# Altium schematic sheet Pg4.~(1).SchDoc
size 431 x 279 mm; Date: Not shown in title block; ApprovedBy: Not shown in title block; CheckedBy: Not shown in title block; Author: Not shown in title block; CompanyName: Not shown in title block; Engineer: Not shown in title block; Organization: Not shown in title block; Address1: Not shown in title block; Address2: Not shown in title block; Address3: Not shown in title block; Address4: Not shown in title block; DocumentNumber: 4; Revision: Use project parameter SCH_Rev; SheetNumber: 4; SheetTotal: 7; PageSetup: Record=PageOptions|CenterHorizontal=True|CenterVertical=True|PrintScale=0.59|XCorrection=1.00|YCorrection=1.00|PrintKind=0|BorderSize=5000000|LeftOffset=0|BottomOffset=0|Orientation=2|PaperLength=1000|PaperWidth=1000|Scale=100|PaperSource=15|PrintQuality=600|MediaType=1|DitherType=10|PaperKind=Letter|PrintScaleMode=1
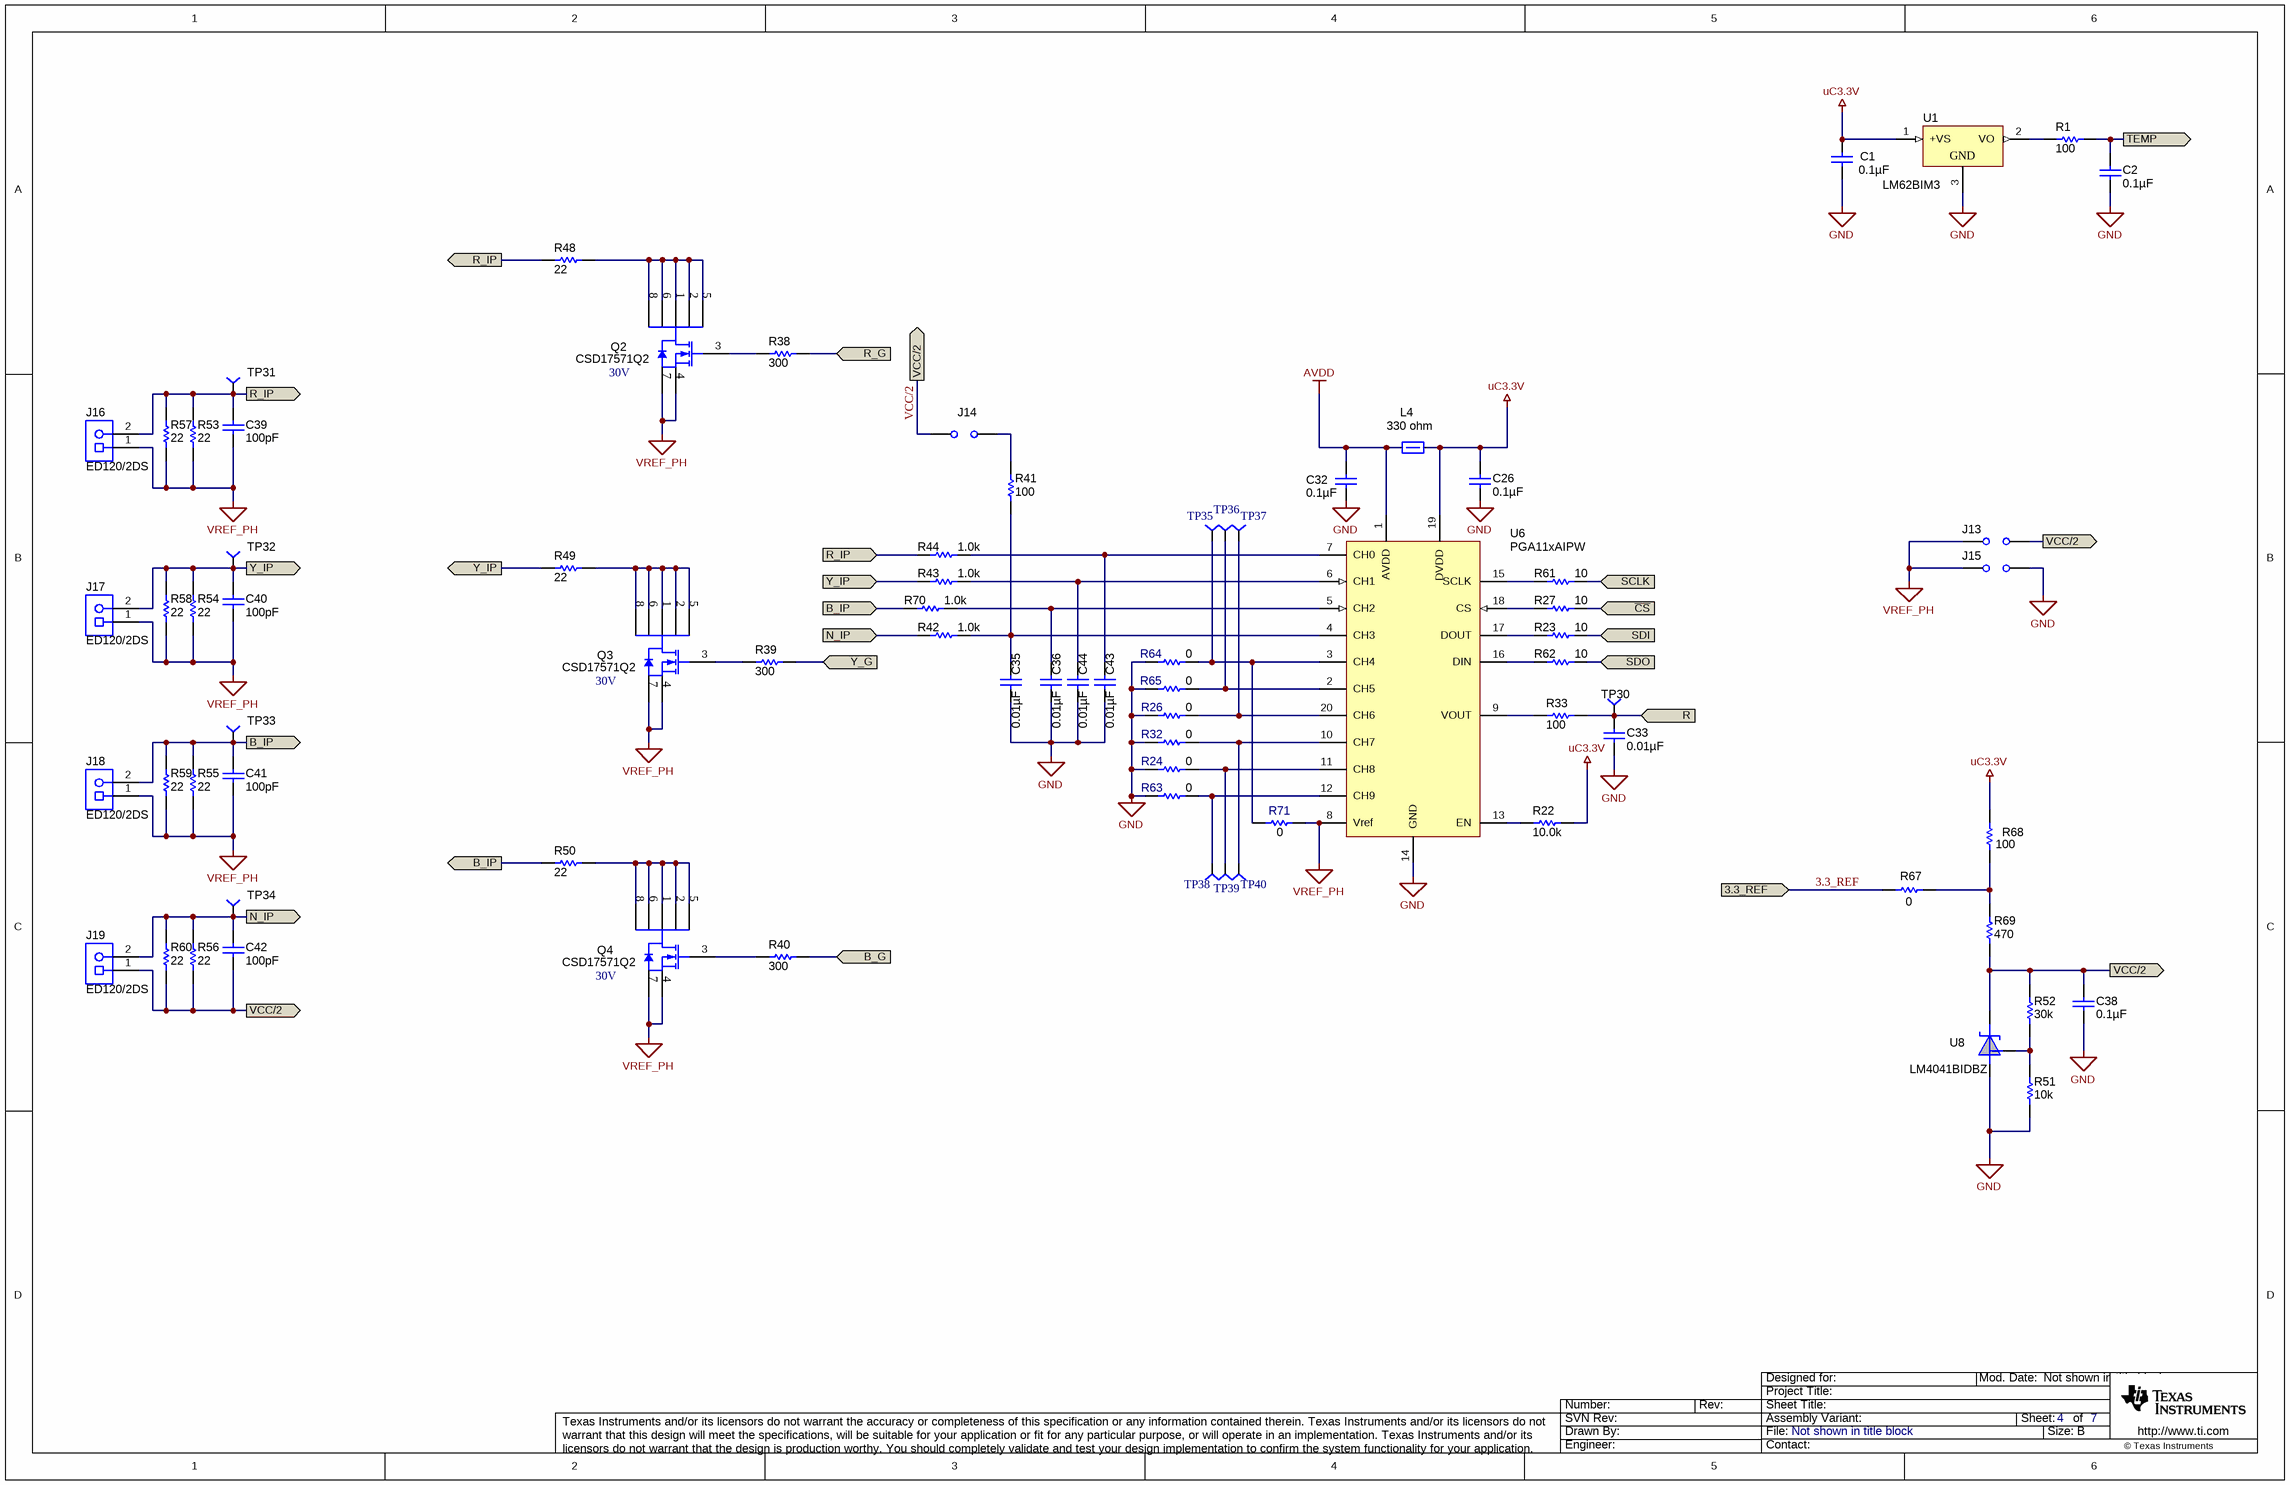
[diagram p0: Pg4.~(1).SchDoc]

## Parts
C1  ValueDisplayed: 0.1µF  [0603]  (hidden comment: 06033C104JAT2A)
C2  ValueDisplayed: 0.1µF  [0603]  (hidden comment: 06033C104JAT2A)
C26  ValueDisplayed: 0.1µF  [0603]  (hidden comment: 06033C104JAT2A)
C32  ValueDisplayed: 0.1µF  [0603]  (hidden comment: 06033C104JAT2A)
C33  ValueDisplayed: 0.01µF  [0603]  (hidden comment: C1608C0G1E103J)
C35  ValueDisplayed: 0.01µF  [0603]  (hidden comment: C1608C0G1E103J)
C36  ValueDisplayed: 0.01µF  [0603]  (hidden comment: C1608C0G1E103J)
C38  ValueDisplayed: 0.1µF  [0603]  (hidden comment: 06033C104JAT2A)
C39  ValueDisplayed: 100pF  [0603]  (hidden comment: 06033C101KAT2A)
C40  ValueDisplayed: 100pF  [0603]  (hidden comment: 06033C101KAT2A)
C41  ValueDisplayed: 100pF  [0603]  (hidden comment: 06033C101KAT2A)
C42  ValueDisplayed: 100pF  [0603]  (hidden comment: 06033C101KAT2A)
C43  ValueDisplayed: 0.01µF  [0603]  (hidden comment: C1608C0G1E103J)
C44  ValueDisplayed: 0.01µF  [0603]  (hidden comment: C1608C0G1E103J)
J13  JUMPER_2X100MIL  [HDR100_1X2]  (value not drawn)
J14  JUMPER_2X100MIL  [HDR100_1X2]  (value not drawn)
J15  JUMPER_2X100MIL  [HDR100_1X2]  (value not drawn)
J16  ED120/2DS  [CONN_ED120-2DS]
J17  ED120/2DS  [CONN_ED120-2DS]
J18  ED120/2DS  [CONN_ED120-2DS]
J19  ED120/2DS  [CONN_ED120-2DS]
L4  value 330 ohm  [0603]  (hidden comment: BLM18SG331TN1D)
Q2  CSD17571Q2  value 30V  [SON_CSD17571Q2]
Q3  CSD17571Q2  value 30V  [SON_CSD17571Q2]
Q4  CSD17571Q2  value 30V  [SON_CSD17571Q2]
R1  value 100  [0603]  (hidden comment: CRCW0603100RFKEA)
R22  value 10.0k  [0603]  (hidden comment: CRCW060310K0FKEA)
R23  value 10  [0603]  (hidden comment: CRCW060310R0JNEA)
R24  value 0  [0603]  (hidden comment: CRCW06030000Z0EA)
R26  value 0  [0603]  (hidden comment: CRCW06030000Z0EA)
R27  value 10  [0603]  (hidden comment: CRCW060310R0JNEA)
R32  value 0  [0603]  (hidden comment: CRCW06030000Z0EA)
R33  value 100  [0603]  (hidden comment: CRCW0603100RFKEA)
R38  value 300  [0603]  (hidden comment: CRCW0603300RJNEA)
R39  value 300  [0603]  (hidden comment: CRCW0603300RJNEA)
R40  value 300  [0603]  (hidden comment: CRCW0603300RJNEA)
R41  value 100  [0603]  (hidden comment: CRCW0603100RFKEA)
R42  value 1.0k  [0603]  (hidden comment: CRCW06031K00JNEA)
R43  value 1.0k  [0603]  (hidden comment: CRCW06031K00JNEA)
R44  value 1.0k  [0603]  (hidden comment: CRCW06031K00JNEA)
R48  value 22  [1206]  (hidden comment: CRCW120622R0JNEA)
R49  value 22  [1206]  (hidden comment: CRCW120622R0JNEA)
R50  value 22  [1206]  (hidden comment: CRCW120622R0JNEA)
R51  value 10k  [0603]  (hidden comment: RNCF0603TKY10K0)
R52  value 30k  [0603]  (hidden comment: CRCW060330K0JNEA)
R53  value 22  [1206]  (hidden comment: CRCW120622R0JNEA)
R54  value 22  [1206]  (hidden comment: CRCW120622R0JNEA)
R55  value 22  [1206]  (hidden comment: CRCW120622R0JNEA)
R56  value 22  [1206]  (hidden comment: CRCW120622R0JNEA)
R57  value 22  [1206]  (hidden comment: CRCW120622R0JNEA)
R58  value 22  [1206]  (hidden comment: CRCW120622R0JNEA)
R59  value 22  [1206]  (hidden comment: CRCW120622R0JNEA)
R60  value 22  [1206]  (hidden comment: CRCW120622R0JNEA)
R61  value 10  [0603]  (hidden comment: CRCW060310R0JNEA)
R62  value 10  [0603]  (hidden comment: CRCW060310R0JNEA)
R63  value 0  [0603]  (hidden comment: CRCW06030000Z0EA)
R64  value 0  [0603]  (hidden comment: CRCW06030000Z0EA)
R65  value 0  [0603]  (hidden comment: CRCW06030000Z0EA)
R67  value 0  [0603]  (hidden comment: CRCW06030000Z0EA)
R68  value 100  [0603]  (hidden comment: CRCW0603100RFKEA)
R69  value 470  [0603]  (hidden comment: CRCW0603470RJNEA)
R70  value 1.0k  [0603]  (hidden comment: CRCW06031K00JNEA)
R71  value 0  [0603]  (hidden comment: CRCW06030000Z0EA)
TP30  TP-040_RND  [TP-040_RND]  (value not drawn)
TP31  TP-040_RND  [TP-040_RND]  (value not drawn)
TP32  TP-040_RND  [TP-040_RND]  (value not drawn)
TP33  TP-040_RND  [TP-040_RND]  (value not drawn)
TP34  TP-040_RND  [TP-040_RND]  (value not drawn)
TP35  TP-040_RND  [TP-040_RND]  (value not drawn)
TP36  TP-040_RND  [TP-040_RND]  (value not drawn)
TP37  TP-040_RND  [TP-040_RND]  (value not drawn)
TP38  TP-040_RND  [TP-040_RND]  (value not drawn)
TP39  TP-040_RND  [TP-040_RND]  (value not drawn)
TP40  TP-040_RND  [TP-040_RND]  (value not drawn)
U1  LM62BIM3  [MF03A_N]
U6  PGA11xAIPW  [PW0020A_L]
U8  LM4041BIDBZ  [SOT-23]

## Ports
3.3_REF (in), B_G (in), B_IP (in), B_IP (out), N_IP (in), N_IP (out), R (in), R_G (in), R_IP (in), R_IP (out), SCLK (in), SDI (in), SDO (in), TEMP (out), VCC/2 (out), Y_G (in), Y_IP (in), Y_IP (out), ~{CS} (in)

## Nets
AVDD: C32.2 L4.1 U6.1(AVDD)
GND: C1.2 C2.1 C26.1 C32.1 C33.2 C35.2 C36.2 C38.1 C43.2 C44.2 J15.2 R24.1 R26.1 R32.1 R51.1 R63.1 R64.1 R65.1 U1.3(GND) U6.14(GND) U8.3(A)
uC3.3V: C1.1 C26.2 L4.2 R22.1 R68.1 U1.1(+VS) U6.19(DVDD)
VREF_PH: C39.2 C40.2 C41.2 J13.1 J15.1 J16.1 J17.1 J18.1 Q2.4(S) Q2.7(S) Q3.4(S) Q3.7(S) Q4.4(S) Q4.7(S) R53.1 R54.1 R55.1 R57.1 R58.1 R59.1 R71.2 U6.8(Vref)
3.3_REF: R67.1 ; port 3.3_REF
~{CS}: R27.2 ; port ~{CS}
B_G: R40.1 ; port B_G
B_IP: C41.1 J18.2 R50.1 R55.2 R59.2 R70.1 TP33.1 ; port B_IP
N_IP: C42.1 J19.2 R42.1 R56.2 R60.2 TP34.1 ; port N_IP
R: C33.1 R33.2 TP30.1 ; port R
R_G: R38.1 ; port R_G
R_IP: C39.1 J16.2 R44.1 R48.1 R53.2 R57.2 TP31.1 ; port R_IP
SCLK: R61.2 ; port SCLK
SDI: R23.2 ; port SDI
SDO: R62.2 ; port SDO
TEMP: C2.2 R1.2 ; port TEMP
VCC/2: C38.2 C42.2 J13.2 J14.2 J19.1 R52.2 R56.1 R60.1 R69.1 U8.2(C) ; port VCC/2
Y_G: R39.1 ; port Y_G
Y_IP: C40.1 J17.2 R43.1 R49.1 R54.2 R58.2 TP32.1 ; port Y_IP
NetC35_1: C35.1 R41.1 R42.2 U6.4(CH3)
NetC36_1: C36.1 R70.2 U6.5(CH2)
NetC43_1: C43.1 R44.2 U6.7(CH0)
NetC44_1: C44.1 R43.2 U6.6(CH1)
NetJ14_1: J14.1 R41.2
NetQ2_1: Q2.1(D) Q2.2(D) Q2.5(D) Q2.6(D) Q2.8(D) R48.2
NetQ2_3: Q2.3(G) R38.2
NetQ3_1: Q3.1(D) Q3.2(D) Q3.5(D) Q3.6(D) Q3.8(D) R49.2
NetQ3_3: Q3.3(G) R39.2
NetQ4_1: Q4.1(D) Q4.2(D) Q4.5(D) Q4.6(D) Q4.8(D) R50.2
NetQ4_3: Q4.3(G) R40.2
NetR1_1: R1.1 U1.2(VO)
NetR22_2: R22.2 U6.13(EN)
NetR23_1: R23.1 U6.17(DOUT)
NetR24_2: R24.2 TP39.1 U6.11(CH8)
NetR26_2: R26.2 TP37.1 U6.20(CH6)
NetR27_1: R27.1 U6.18(CS)
NetR32_2: R32.2 TP40.1 U6.10(CH7)
NetR33_1: R33.1 U6.9(VOUT)
NetR51_2: R51.2 R52.1 U8.1(FB)
NetR61_1: R61.1 U6.15(SCLK)
NetR62_1: R62.1 U6.16(DIN)
NetR63_2: R63.2 TP38.1 U6.12(CH9)
NetR64_2: R64.2 R71.1 TP35.1 U6.3(CH4)
NetR65_2: R65.2 TP36.1 U6.2(CH5)
NetR67_2: R67.2 R68.2 R69.2

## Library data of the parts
C1 C2 C26 C32 C38 = 06033C104JAT2A: CAP, CERM, 0.1uF, 25V, +/-5%, X7R, 0603; Manufacturer: AVX; Polarized: N; CompType: Capacitor; U/M: EA; Cap_F: 0.0000001; Tolerance_%: 5; ESR_Ohm: 0.05; Value1: 0.05 ohm; VDC_V: 25; TaMin_C: -55; TaMax_C: 125
C33 C35 C36 C43 C44 = C1608C0G1E103J: CAP, CERM, 0.01uF, 25V, +/-5%, C0G/NP0, 0603; Manufacturer: TDK; Polarized: N; CompType: Capacitor; U/M: EA; Cap_F: 0.00000001; Tolerance_%: 5; Value1: Unknown; VDC_V: 25; TaMin_C: -55; TaMax_C: 125
C39-C42 = 06033C101KAT2A: CAP, CERM, 100pF, 25V, +/-10%, X7R, 0603; Manufacturer: AVX; Polarized: N; CompType: Capacitor; U/M: EA; Cap_F: 0.0000000001; Tolerance_%: 10; Value1: Unknown; VDC_V: 25; TaMin_C: -55; TaMax_C: 125
J13-J15 = JUMPER_2X100MIL: Header, Male 2-pin, 100mil spacing,; Manufacturer: Sullins; PartNumber: PEC02SAAN; area: 20000; Value: PEC02SAAN
J16-J19 = ED120/2DS: TERMINAL BLOCK 5.08MM VERT 2POS, TH; Manufacturer: On-Shore Technology; SymbolCreator: a0412235; U/M: EA
L4 = BLM18SG331TN1D: 1.5A Ferrite Bead, 330 ohm @ 100MHz, SMD; Manufacturer: MuRata; Imax_A: 1.5; DCR_ohm: 0.07; Value1: 0.07 ohm; ZTyp@100MHz_Ohm: 330; U/M: EA
Q2-Q4 = CSD17571Q2: MOSFET, N-CH, 30V, 22A, SON 2X2 MM; Manufacturer: TEXAS INSTRUMENTS; CompType: POWER MOSFET
R1 R33 R41 R68 = CRCW0603100RFKEA: RES, 100 ohm, 1%, 0.1W, 0603; Manufacturer: Vishay-Dale; CompType: Resistor; Value_Code: 100R; Tolerance_%: 1; Power_W: 0.1; VDC_V: 75; TempCo: 100 ppm/C; EIA_Code: E96; U/M: EA
R22 = CRCW060310K0FKEA: RES, 10.0k ohm, 1%, 0.1W, 0603; Manufacturer: Vishay-Dale; CompType: Resistor; Res_ohm: 10000; Value_Code: 10k0; Tolerance_%: 1; Power_W: 0.1; VDC_V: 75; TempCo: 100 ppm/C; EIA_Code: E96; U/M: EA
R23 R27 R61 R62 = CRCW060310R0JNEA: RES, 10 ohm, 5%, 0.1W, 0603; Manufacturer: Vishay-Dale; CompType: Resistor; Value_Code: 10R0; Tolerance_%: 5; Power_W: 0.1; VDC_V: 75; TempCo: 200 ppm/C; EIA_Code: E24; U/M: EA
R24 R26 R32 R63-R65 R67 R71 = CRCW06030000Z0EA: RES, 0 ohm, 5%, 0.1W, 0603; Manufacturer: Vishay-Dale; CompType: Resistor; Value_Code: 0000; Tolerance_%: 5; Power_W: 0.1; VDC_V: 75; TempCo: 200 ppm/C; EIA_Code: E24; U/M: EA
R38-R40 = CRCW0603300RJNEA: RES, 300 ohm, 5%, 0.1W, 0603; Manufacturer: Vishay-Dale; CompType: Resistor; Value_Code: 300R; Tolerance_%: 5; Power_W: 0.1; VDC_V: 75; TempCo: 200 ppm/C; EIA_Code: E24; U/M: EA
R42-R44 R70 = CRCW06031K00JNEA: RES, 1.0k ohm, 5%, 0.1W, 0603; Manufacturer: Vishay-Dale; CompType: Resistor; Res_ohm: 1000; Value_Code: 1k00; Tolerance_%: 5; Power_W: 0.1; VDC_V: 75; TempCo: 200 ppm/C; EIA_Code: E24; U/M: EA
R48-R50 R53-R60 = CRCW120622R0JNEA: RES, 22 ohm, 5%, 0.25W, 1206; Manufacturer: Vishay-Dale; CompType: Resistor; Value_Code: 22R0; Tolerance_%: 5; Power_W: 0.25; VDC_V: 200; TempCo: 200 ppm/C; EIA_Code: E24; U/M: EA
R51 = RNCF0603TKY10K0: RES, 10k ohm, 0.01%, 0.063W, 0603; Manufacturer: Stackpole Electronics Inc; CompType: Resistor; Res_ohm: 10000; Value_Code: 10k0; Tolerance_%: 0.01; Power_W: 0.063; VDC_V: 50; TempCo: 5 ppm/C; U/M: EA
R52 = CRCW060330K0JNEA: RES, 30k ohm, 5%, 0.1W, 0603; Manufacturer: Vishay-Dale; CompType: Resistor; Res_ohm: 30000; Value_Code: 30k0; Tolerance_%: 5; Power_W: 0.1; VDC_V: 75; TempCo: 200 ppm/C; EIA_Code: E24; U/M: EA
R69 = CRCW0603470RJNEA: RES, 470 ohm, 5%, 0.1W, 0603; Manufacturer: Vishay-Dale; CompType: Resistor; Value_Code: 470R; Tolerance_%: 5; Power_W: 0.1; VDC_V: 75; TempCo: 200 ppm/C; EIA_Code: E24; U/M: EA
TP30-TP40 = TP-040_RND: Test Point, O.040 Hole; Manufacturer: STD; Value: STD
U1 = LM62BIM3: 2.7V, 15.6mV/°C, Temperature Sensor, 3-pin SOT-23; Manufacturer: National Semiconductor; PackageTopMarking: T7B*XTT; PowerWise: N; CompType: Temp Sensor IC
U6 = PGA11xAIPW: ZerØ-Drift Programmable Gain Amplifier with MUX; Alternate Manufacturer: None; Manufacturer: Texas Instruments; SymbolCreator: x0120606; CompType: IC
U8 = LM4041BIDBZ: IC, Micropower Shunt Voltage Reference 100 ppm/°C, 45µA-12mA,  Adjustable; Manufacturer: TI; Alternate Manufacturer: None; Area: 25500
